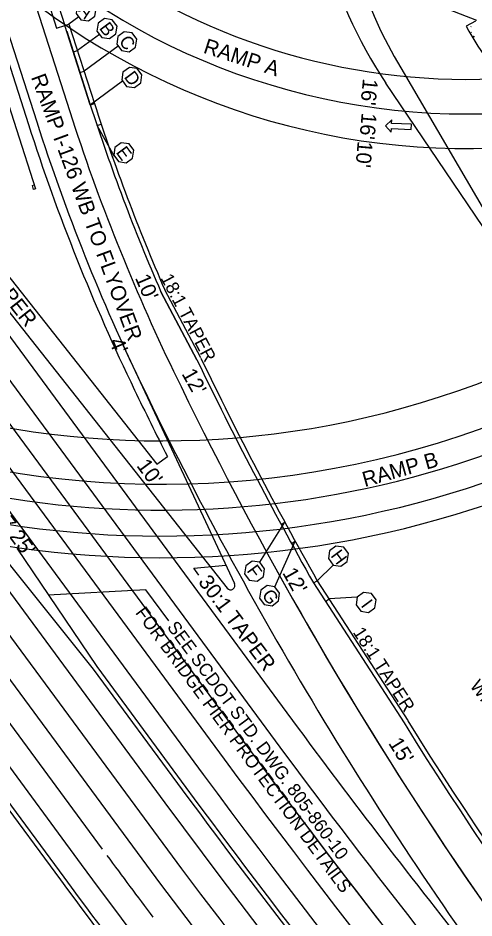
# Model space of a CAD drawing. Extents: x 1966090 to 1975830, y 788086 to 801233.
# Drawn here: x 1971144.7 to 1971355.4, y 795877.6 to 796293.3 of the extents above; entities that cross this region are included whole.
import ezdxf

# ---------------------------------------------------------------- set-up
doc = ezdxf.new("R2010")
doc.units = 0
for name, color, linetype in [('BR_PRESTRESSED BEAM', 7, 'Continuous'), ('BR_PROPOSED_DRAINAGE', 7, 'Continuous'), ('BR_REBAR', 7, 'Continuous'), ('BR_SITE LOCATION', 7, 'Continuous'), ('RD_EX_Driveway_txCode', 7, 'Continuous'), ('RD_EX_SU_Gas', 7, 'Continuous'), ('RD_EX_SU_H2O', 7, 'Continuous'), ('RD_EX_TX_Dam_ELEV', 7, 'Continuous'), ('RD_PD_PaveShd', 7, 'Continuous'), ('RD_PD_RW_TX', 7, 'Continuous'), ('RD_Sketch1', 7, 'Continuous'), ('RD_Sketch6', 7, 'Continuous'), ('RD_Sketch8', 7, 'Continuous')]:
    doc.layers.add(name, color=color, linetype=linetype)

msp = doc.modelspace()

# ---------------------------------------------------------------- linework, layer by layer
at = {"layer": 'BR_PRESTRESSED BEAM'}
for p, q in [((1971155.03, 796325.07), (1971166.35, 796289.84)), ((1971130.78, 796282.88), (1971152.81, 796214.33)), ((1971151.48, 796216.01), (1971152.2, 796216.24)), ((1971151.86, 796214.03), (1971151.48, 796216.01)), ((1971152.2, 796216.24), (1971152.81, 796214.33)), ((1971152.81, 796214.33), (1971151.86, 796214.03)), ((1971060.28, 796036.33), (1971164.29, 795895.24))]:
    msp.add_line(p, q, dxfattribs=at)
msp.add_arc((1974296, 798203.94), 3890.72, 216.39766, 221.64292, dxfattribs=at)
at = {"layer": 'BR_PROPOSED_DRAINAGE'}
msp.add_line((1971321.61, 796270.35), (1971480.17, 795998.61), dxfattribs=at)
msp.add_arc((1971482.81, 796369.08), 189.03, 197.0542, 211.4852, dxfattribs=at)
at = {"layer": 'BR_REBAR'}
for p, q in [((1971166.35, 796289.84), (1971168.26, 796290.45)), ((1971168.26, 796290.45), (1971180.02, 796253.85)), ((1971167.22, 796287.15), (1971178.12, 796253.24)), ((1971170.28, 796277.63), (1971172.18, 796278.24)), ((1971173.34, 796268.11), (1971175.24, 796268.72)), ((1971178.15, 796253.14), (1971180.05, 796253.75)), ((1971181.27, 796243.62), (1971183.17, 796244.25)), ((1971227.37, 796135.4), (1971210.72, 796166.89)), ((1971229.14, 796136.33), (1971212.52, 796167.76)), ((1971266.26, 796059.45), (1971268.02, 796060.4)), ((1971271.06, 796050.65), (1971272.81, 796051.63)), ((1971281.23, 796032.39), (1971282.98, 796033.37)), ((1971281.23, 796032.39), (1971323.07, 795967.72)), ((1971282.95, 796033.42), (1971324.75, 795968.81)), ((1971286.73, 796023.89), (1971288.41, 796024.98))]:
    msp.add_line(p, q, dxfattribs=at)
for centre, radius, start, end in [((1972056.84, 796535.68), 923, 197.81866, 203.55032), ((1972056.84, 796535.68), 921, 197.81866, 203.54563), ((1972855.69, 796921.19), 1806, 205.76109, 209.44351), ((1972855.69, 796921.19), 1808, 205.76109, 209.44542), ((1972855.69, 796921.19), 1805, 211.88652, 221.68841), ((1972855.69, 796921.19), 1803, 211.88652, 221.68841)]:
    msp.add_arc(centre, radius, start, end, dxfattribs=at)
at = {"layer": 'BR_SITE LOCATION'}
for p, q in [((1971356.11, 796291.89), (1971351.73, 796289.49)), ((1971353.9, 796289.29), (1971354.08, 796289.32)), ((1971354.19, 796286.71), (1971354.14, 796286.58))]:
    msp.add_line(p, q, dxfattribs=at)
for points in [[(1971351.73, 796289.49), (1971352.93, 796287.27), (1971357.17, 796280.35), (1971358.53, 796278.28), (1971373.56, 796256.05), (1971390.85, 796230.96), (1971410.3, 796202.74), (1971488.36, 796090.96), (1971513.02, 796056.01)], [(1971354.86, 796284.82), (1971355.37, 796284.89), (1971355.34, 796284.43), (1971354.86, 796284.82)]]:
    msp.add_lwpolyline(points, dxfattribs=at)
at = {"layer": 'RD_EX_Driveway_txCode'}
for p, q in [((1971225.95, 796039.21), (1971240.76, 796040.62)), ((1971228.32, 796035.99), (1971225.95, 796039.21))]:
    msp.add_line(p, q, dxfattribs=at)
msp.add_lwpolyline([(1971326.4, 796241.82), (1971326.5, 796244.22), (1971317.34, 796244.63), (1971317.41, 796246.25), (1971314.46, 796243.55), (1971317.16, 796240.6), (1971317.23, 796242.23)], close=True, dxfattribs=at)
at = {"layer": 'RD_EX_SU_Gas'}
for p, q in [((1970505.09, 796947.85), (1971239.95, 795951.02)), ((1970468.06, 796920.55), (1971202.93, 795923.73)), ((1970458.41, 796913.43), (1971193.27, 795916.61)), ((1971016.36, 796136.35), (1971183.61, 795909.49)), ((1971131.76, 796118.01), (1971249.61, 795958.14))]:
    msp.add_line(p, q, dxfattribs=at)
for centre, radius, start, end in [((1971210.82, 796516.01), 450, 239.8879, 298.9233), ((1974296, 798203.94), 3784.72, 216.39766, 226.1479), ((1974296, 798203.94), 3784.72, 216.39766, 236.97136), ((1974296, 798203.94), 3796.72, 216.39766, 236.97136), ((1974296, 798203.94), 3842.72, 216.39766, 244.09898), ((1974296, 798203.94), 3854.72, 216.39766, 243.9112), ((1974296, 798203.94), 3866.72, 216.4518, 216.97913)]:
    msp.add_arc(centre, radius, start, end, dxfattribs=at)
at = {"layer": 'RD_EX_TX_Dam_ELEV'}
msp.add_lwpolyline([(1971469.8, 796034.17), (1971314.72, 796263.25)], dxfattribs=at)
msp.add_arc((1971479.12, 796374.54), 198.53, 173.0345, 214.0973, dxfattribs=at)
at = {"layer": 'RD_PD_PaveShd'}
for p, q in [((1971104.45, 796469.35), (1971162.54, 796288.62)), ((1971079.7, 796461.4), (1971149.56, 796244.06)), ((1971162.54, 796288.62), (1971166.35, 796289.84)), ((1971178.12, 796253.24), (1971166.35, 796289.84)), ((1971063.23, 796271.64), (1971208.88, 796087.26)), ((1971210.72, 796166.89), (1971227.37, 796135.4)), ((1971208.88, 796087.26), (1971213.71, 796090.82)), ((1971144.16, 796048.52), (1971181.11, 795993.76)), ((1971138.13, 796044.07), (1971179.5, 795992.57)), ((1971061.89, 796037.52), (1971165.9, 795896.43)), ((1971281.23, 796032.39), (1971323.07, 795967.72)), ((1971179.5, 795992.57), (1971220.63, 795936.78)), ((1971181.11, 795993.76), (1971222.24, 795937.97))]:
    msp.add_line(p, q, dxfattribs=at)
for centre, radius, start, end in [((1972056.84, 796535.68), 923, 197.81866, 203.55032), ((1972056.84, 796535.68), 953, 197.81866, 205.76109), ((1971210.82, 796516.01), 418, 222.4751, 298.9233), ((1972855.69, 796921.19), 1808, 205.76109, 209.44542), ((1971210.82, 796516.01), 472, 234.9869, 298.9233), ((1972855.69, 796921.19), 1840, 205.76109, 206.82633), ((1972855.69, 796921.19), 1805, 211.88652, 221.68841), ((1974296, 798203.94), 3820.72, 216.39766, 219.56665), ((1974296, 798203.94), 3818.72, 216.39766, 219.56614), ((1974296, 798203.94), 3888.72, 216.39766, 221.6415)]:
    msp.add_arc(centre, radius, start, end, dxfattribs=at)
at = {"layer": 'RD_PD_RW_TX'}
msp.add_arc((1971352.19, 796562.97), 298, 221.212, 301.3407, dxfattribs=at)
at = {"layer": 'RD_Sketch1'}
msp.add_arc((1972855.69, 796921.19), 1820, 209.01045, 218.45481, dxfattribs=at)
at = {"layer": 'RD_Sketch6'}
for p, q in [((1971356.73, 796292.22), (1971325.67, 796304.26)), ((1971172.75, 796293.78), (1971168.26, 796290.45)), ((1971182.32, 796285.74), (1971172.18, 796278.24)), ((1971190.92, 796280.32), (1971175.24, 796268.72)), ((1971193.05, 796264.17), (1971178.15, 796253.14)), ((1971189.29, 796229.4), (1971181.27, 796243.62)), ((1971256.47, 796041.91), (1971268.02, 796060.4)), ((1971263.42, 796030.61), (1971272.81, 796051.63)), ((1971290.3, 796040.66), (1971282.95, 796033.42)), ((1971203.76, 796029.25), (1971158.71, 796026.8)), ((1971214.35, 796014.88), (1971203.76, 796029.25)), ((1971301.45, 796025.87), (1971288.41, 796024.98))]:
    msp.add_line(p, q, dxfattribs=at)
for points in [[(1971177.31, 796291.96), (1971180.25, 796294.14), (1971180.79, 796297.75), (1971178.61, 796300.69), (1971175, 796301.23), (1971172.06, 796299.06), (1971171.52, 796295.44), (1971173.69, 796292.5)], [(1971186.99, 796283.78), (1971189.93, 796285.95), (1971190.47, 796289.57), (1971188.29, 796292.51), (1971184.68, 796293.05), (1971181.74, 796290.88), (1971181.2, 796287.26), (1971183.37, 796284.32)], [(1971196.09, 796277.69), (1971199.03, 796279.86), (1971199.57, 796283.48), (1971197.4, 796286.42), (1971193.78, 796286.96), (1971190.84, 796284.78), (1971190.3, 796281.17), (1971192.48, 796278.23)], [(1971198.47, 796261.19), (1971201.41, 796263.37), (1971201.95, 796266.98), (1971199.77, 796269.92), (1971196.16, 796270.46), (1971193.22, 796268.29), (1971192.68, 796264.67), (1971194.85, 796261.73)], [(1971194.71, 796226.42), (1971197.65, 796228.59), (1971198.19, 796232.21), (1971196.02, 796235.15), (1971192.4, 796235.69), (1971189.46, 796233.52), (1971188.92, 796229.9), (1971191.1, 796226.96)], [(1971293.92, 796040.12), (1971296.86, 796042.3), (1971297.4, 796045.92), (1971295.22, 796048.86), (1971291.6, 796049.4), (1971288.67, 796047.22), (1971288.12, 796043.6), (1971290.3, 796040.66)], [(1971255.17, 796033.18), (1971258.11, 796035.36), (1971258.65, 796038.97), (1971256.47, 796041.91), (1971252.85, 796042.45), (1971249.91, 796040.28), (1971249.37, 796036.66), (1971251.55, 796033.72)], [(1971262.11, 796021.88), (1971265.05, 796024.06), (1971265.59, 796027.67), (1971263.42, 796030.61), (1971259.8, 796031.15), (1971256.86, 796028.98), (1971256.32, 796025.36), (1971258.49, 796022.42)], [(1971306.7, 796018.77), (1971309.64, 796020.95), (1971310.18, 796024.56), (1971308, 796027.5), (1971304.39, 796028.04), (1971301.45, 796025.87), (1971300.91, 796022.25), (1971303.08, 796019.31)]]:
    msp.add_lwpolyline(points, close=True, dxfattribs=at)
at = {"layer": 'RD_Sketch8'}
for p, q in [((1970534.07, 796969.21), (1971268.93, 795972.38)), ((1970524.41, 796962.09), (1971259.27, 795965.26)), ((1970495.43, 796940.73), (1971230.29, 795943.9)), ((1970477.72, 796927.67), (1971212.58, 795930.85)), ((1970686.68, 796563.34), (1971173.95, 795902.36)), ((1971098.74, 796467.52), (1971168.6, 796250.18)), ((1971083.51, 796462.62), (1971153.36, 796245.28)), ((1971018.07, 796312.68), (1971241.34, 796030.03)), ((1971193.35, 796142), (1971244.7, 796032.18))]:
    msp.add_line(p, q, dxfattribs=at)
for centre, radius, start, end in [((1971352.19, 796562.97), 314, 221.212, 318.863), ((1971352.19, 796562.97), 330, 221.212, 316.8104), ((1971210.82, 796516.01), 438, 216.3977, 298.9233), ((1972056.84, 796535.68), 933, 197.81866, 205.76109), ((1972056.84, 796535.68), 949, 197.81866, 205.76109), ((1971210.82, 796516.01), 462, 234.9869, 298.9233), ((1972855.69, 796921.19), 1820, 205.76109, 221.68841), ((1972855.69, 796921.19), 1836, 205.76109, 216.40394), ((1971242.95, 796031.21), 2, 216.3977, 28.8919), ((1974296, 798203.94), 3760.72, 216.39766, 218.51982), ((1974296, 798203.94), 3772.72, 216.39766, 219.89735), ((1974296, 798203.94), 3808.72, 216.39766, 236.97136), ((1974296, 798203.94), 3830.72, 216.39766, 243.9112), ((1974296, 798203.94), 3878.72, 216.39766, 241.30888)]:
    msp.add_arc(centre, radius, start, end, dxfattribs=at)

# ---------------------------------------------------------------- texts
at = {"layer": 'RD_EX_Driveway_txCode'}
for s, rotation, p in [('RAMP I-126 WB TO FLYOVER', 290.255, (1971150.62, 796266)), ("16'", 264.3642, (1971304.12, 796265.5)), ("16'", 265.0212, (1971303.52, 796249.66)), ("10'", 265.0212, (1971301.68, 796236.67)), ('30:1 TAPER', 308.3068, (1971116.34, 796190.87)), ("10'", 293.2416, (1971198.66, 796173.29)), ("4'", 292.3934, (1971186.7, 796143.95)), ("12'", 299.265, (1971220.13, 796129.03)), ("10'", 306.3992, (1971199.2, 796086.5)), ("7.25'", 306.2638, (1971135.78, 796060.05)), ("12'", 299.265, (1971266.68, 796037.09)), ('30:1 TAPER', 306.5095, (1971227.71, 796032.81)), ("15'", 301.844, (1971315.62, 795958.37))]:
    msp.add_text(s, height=7, rotation=rotation, dxfattribs=at).set_placement(p)
at = {"layer": 'RD_EX_SU_H2O'}
for s, rotation, p in [('RAMP A', 341.9931, (1971229.94, 796277.36)), ('RAMP B', 15.8135, (1971304.93, 796076.62))]:
    msp.add_text(s, height=7, rotation=rotation, dxfattribs=at).set_placement(p)
at = {"layer": 'RD_Sketch6'}
for s, height, rotation, p in [('A', 6, 306.5054, (1971172.29, 796296.77)), ('B', 6, 306.5054, (1971181.97, 796288.59)), ('C', 6, 306.5054, (1971191.08, 796282.49)), ('D', 6, 306.5054, (1971193.45, 796266)), ('E', 6, 306.5054, (1971189.7, 796231.23)), ('18:1 TAPER', 6, 297.8012, (1971210.42, 796173.26)), ('H', 6, 306.5054, (1971288.9, 796044.93)), ('F', 6, 306.5054, (1971250.15, 796037.99)), ('G', 6, 306.5054, (1971257.1, 796026.69)), ('I', 6, 306.5054, (1971302.87, 796021.97)), ('FOR BRIDGE PIER PROTECTION DETAILS', 6, 306.396, (1971198.67, 796018.58)), ('SEE SCDOT STD. DWG. 805-860-10', 6, 306.396, (1971213.33, 796011.96)), ('18:1 TAPER', 6, 302.8665, (1971299.2, 796009.61)), ('WITH BARRIER', 5.9996, 306.5574, (1971353.23, 795984.8)), ('CONSTRUCT MTBBC3 (MASH) THRIE-BEAM', 5.9996, 306.4243, (1971056.11, 795968.49))]:
    msp.add_text(s, height=height, rotation=rotation, dxfattribs=at).set_placement(p)

doc.saveas('drawing.dxf')
